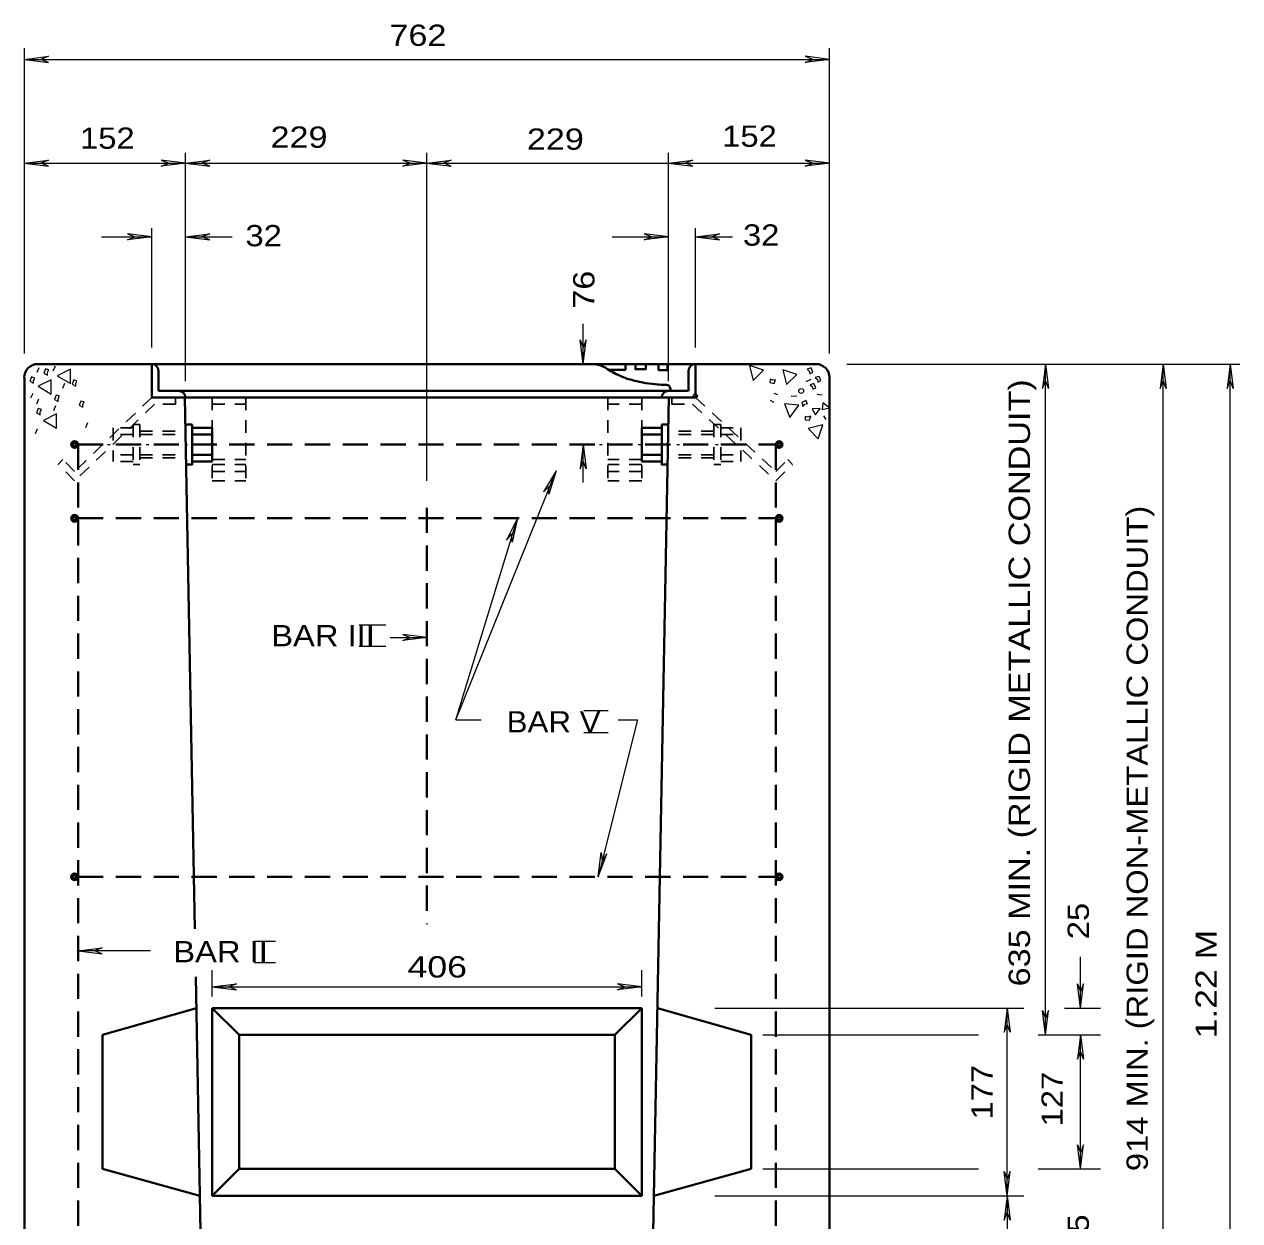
# Model space of a CAD drawing. Extents: x 312583 to 312854, y 144419 to 144597.
# Drawn here: x 312697 to 312740.39, y 144467.02 to 144509.75 of the extents above; entities that cross this region are included whole.
import ezdxf

# ---------------------------------------------------------------- set-up
doc = ezdxf.new("R2010")
doc.units = 0
doc.header["$LTSCALE"] = 0.3
doc.header["$PDMODE"] = 32
doc.header["$PDSIZE"] = 0.15
for name, pattern in [('DOTTED', [1.5, 0.3, -1.2]), ('MEDIUM_DASHED', [4.5, 3, -1.5]), ('SHORT_DASHED', [2.7, 1.5, -1.2])]:
    doc.linetypes.add(name, pattern=pattern)
doc.layers.add('1', color=7, linetype='Continuous', lineweight=25)
doc.layers.add('2', color=7, linetype='Continuous', lineweight=13)

msp = doc.modelspace()

# ---------------------------------------------------------------- linework, layer by layer
at = {"layer": '1', "lineweight": 13}
for p, q in [((312697.5224, 144497.485), (312697.4457, 144497.3164)), ((312698.0974, 144497.5387), (312698.0207, 144497.3624)), ((312697.3, 144496.565), (312697.2234, 144496.3964)), ((312698.4347, 144496.9177), (312698.358, 144496.749)), ((312697.507, 144496.358), (312697.4304, 144496.1894)), ((312698.1127, 144496.1204), (312698.036, 144495.9517)), ((312697.461, 144495.2924), (312697.3844, 144495.1237)), ((312699.255, 144495.5147), (312699.186, 144495.3384))]:
    msp.add_line(p, q, dxfattribs=at)
at = {"layer": '1', "lineweight": 40}
for p, q in [((312697.4764, 144497.6154), (312725.268, 144497.6154)), ((312701.5474, 144497.6154), (312701.5474, 144496.4194)), ((312720.9594, 144497.6154), (312720.9594, 144496.4194)), ((312697.001, 144497.14), (312697.001, 144451.6154)), ((312701.7927, 144497.3777), (312701.7927, 144496.657)), ((312720.714, 144497.3777), (312720.714, 144496.657)), ((312725.751, 144497.14), (312725.751, 144451.6154)), ((312701.7927, 144496.657), (312720.714, 144496.657)), ((312701.5474, 144496.4194), (312720.9594, 144496.4194)), ((312702.728, 144496.4194), (312703.0884, 144477.4444)), ((312720.0164, 144496.4194), (312719.2804, 144457.3654)), ((312702.9887, 144495.461), (312702.751, 144495.461)), ((312702.9887, 144495.3384), (312703.7094, 144495.3384)), ((312703.7094, 144495.3384), (312703.7094, 144494.1424)), ((312719.0427, 144495.3384), (312719.0427, 144494.1424)), ((312719.7557, 144495.3384), (312719.0427, 144495.3384)), ((312719.7557, 144495.461), (312720.001, 144495.461)), ((312702.9887, 144495.1007), (312703.7094, 144495.1007)), ((312719.7557, 144495.1007), (312719.0427, 144495.1007)), ((312702.9887, 144494.38), (312703.7094, 144494.38)), ((312702.9887, 144494.1424), (312703.7094, 144494.1424)), ((312719.7557, 144494.38), (312719.0427, 144494.38)), ((312719.7557, 144494.1424), (312719.0427, 144494.1424)), ((312703.119, 144475.727), (312703.464, 144457.3654)), ((312703.142, 144474.6154), (312699.7917, 144473.657)), ((312703.7094, 144474.6154), (312719.0427, 144474.6154)), ((312703.7094, 144474.6154), (312703.7094, 144467.907)), ((312704.6677, 144473.657), (312703.7094, 144474.6154)), ((312718.0844, 144473.657), (312719.0427, 144474.6154)), ((312719.0427, 144474.6154), (312719.0427, 144467.907)), ((312719.6024, 144474.6154), (312722.9527, 144473.657)), ((312699.7917, 144473.657), (312699.7917, 144468.8654)), ((312704.6677, 144473.657), (312718.0844, 144473.657)), ((312704.6677, 144473.657), (312704.6677, 144468.8654)), ((312718.0844, 144473.657), (312718.0844, 144468.8654)), ((312722.9527, 144473.657), (312722.9527, 144468.8654)), ((312699.7917, 144468.8654), (312703.2647, 144467.907)), ((312704.6677, 144468.8654), (312703.7094, 144467.907)), ((312704.6677, 144468.8654), (312718.0844, 144468.8654)), ((312719.0427, 144467.907), (312718.0844, 144468.8654)), ((312722.9527, 144468.8654), (312719.4797, 144467.907)), ((312703.7094, 144467.907), (312719.0427, 144467.907))]:
    msp.add_line(p, q, dxfattribs=at)
at = {"layer": '1', "linetype": 'SHORT_DASHED'}
for p, q in [((312701.5474, 144496.4194), (312698.795, 144493.782)), ((312701.647, 144496.1817), (312698.795, 144493.4447)), ((312702.3907, 144496.1817), (312701.647, 144496.1817)), ((312702.3907, 144496.4194), (312702.3907, 144496.1817)), ((312703.7094, 144496.4194), (312703.7094, 144493.4447)), ((312703.7094, 144496.1817), (312704.9054, 144496.1817)), ((312704.9054, 144496.4194), (312704.9054, 144493.4447)), ((312717.839, 144496.4194), (312717.839, 144493.4447)), ((312719.0427, 144496.1817), (312717.839, 144496.1817)), ((312719.0427, 144496.4194), (312719.0427, 144493.4447)), ((312720.116, 144496.4194), (312720.116, 144496.1817)), ((312720.116, 144496.1817), (312720.8597, 144496.1817)), ((312720.8597, 144496.1817), (312723.8344, 144493.4447)), ((312720.9594, 144496.4194), (312723.8344, 144493.782)), ((312700.1674, 144495.3384), (312700.1674, 144494.1424)), ((312700.888, 144495.3384), (312700.1674, 144495.3384)), ((312700.888, 144495.461), (312700.888, 144494.0274)), ((312700.888, 144495.461), (312701.1257, 144495.461)), ((312701.1257, 144495.461), (312701.1257, 144494.0274)), ((312721.6187, 144495.461), (312721.6187, 144494.0274)), ((312721.864, 144495.461), (312721.6187, 144495.461)), ((312721.864, 144495.461), (312721.864, 144494.0274)), ((312721.864, 144495.3384), (312722.577, 144495.3384)), ((312722.577, 144495.3384), (312722.577, 144494.1424)), ((312700.888, 144495.1007), (312700.1674, 144495.1007)), ((312701.1257, 144495.2234), (312702.751, 144495.2234)), ((312701.1257, 144495.1007), (312702.751, 144495.1007)), ((312721.6187, 144495.2234), (312720.001, 144495.2234)), ((312721.6187, 144495.1007), (312720.001, 144495.1007)), ((312721.864, 144495.1007), (312722.577, 144495.1007)), ((312698.3734, 144494.2037), (312698.2047, 144494.035)), ((312698.795, 144493.4447), (312698.2047, 144494.035)), ((312698.795, 144493.782), (312698.3734, 144494.2037)), ((312700.888, 144494.38), (312700.1674, 144494.38)), ((312700.888, 144494.1424), (312700.1674, 144494.1424)), ((312700.888, 144494.0274), (312701.1257, 144494.0274)), ((312701.1257, 144494.38), (312702.751, 144494.38)), ((312701.1257, 144494.265), (312702.751, 144494.265)), ((312703.7094, 144494.2037), (312704.9054, 144494.2037)), ((312703.7094, 144494.035), (312704.9054, 144494.035)), ((312719.0427, 144494.2037), (312717.839, 144494.2037)), ((312719.0427, 144494.035), (312717.839, 144494.035)), ((312721.6187, 144494.38), (312720.001, 144494.38)), ((312721.6187, 144494.265), (312720.001, 144494.265)), ((312721.864, 144494.0274), (312721.6187, 144494.0274)), ((312721.864, 144494.38), (312722.577, 144494.38)), ((312721.864, 144494.1424), (312722.577, 144494.1424)), ((312723.8344, 144493.782), (312724.256, 144494.2037)), ((312723.8344, 144493.4447), (312724.4247, 144494.035)), ((312724.256, 144494.2037), (312724.4247, 144494.035)), ((312703.7094, 144493.782), (312704.9054, 144493.782)), ((312719.0427, 144493.782), (312717.839, 144493.782)), ((312703.7094, 144493.4447), (312704.9054, 144493.4447)), ((312719.0427, 144493.4447), (312717.839, 144493.4447))]:
    msp.add_line(p, q, dxfattribs=at)
at = {"layer": '1', "linetype": 'MEDIUM_DASHED', "lineweight": 40}
for p, q in [((312698.9177, 144494.7404), (312698.9177, 144452.9187)), ((312698.9177, 144494.7404), (312723.8344, 144494.7404)), ((312723.8344, 144494.7404), (312723.8344, 144452.9187)), ((312711.376, 144492.4864), (312711.376, 144477.6054)), ((312698.9177, 144492.1107), (312723.8344, 144492.1107)), ((312698.9177, 144479.2997), (312723.8344, 144479.2997))]:
    msp.add_line(p, q, dxfattribs=at)
at = {"layer": '1', "linetype": 'DOTTED', "lineweight": 13}
for p, q in [((312699.968, 144494.7404), (312704.0007, 144494.7404)), ((312716.6124, 144494.7404), (312722.9067, 144494.7404))]:
    msp.add_line(p, q, dxfattribs=at)
at = {"layer": '1', "lineweight": 13}
for points in [[(312697.829, 144497.324), (312697.875, 144497.4084), (312697.76, 144497.4467), (312697.6987, 144497.2934), (312697.829, 144497.2167)], [(312698.6417, 144496.9177), (312698.6417, 144497.439), (312698.174, 144497.2014)], [(312697.323, 144497.0327), (312697.369, 144497.117), (312697.254, 144497.1554), (312697.1927, 144497.002), (312697.323, 144496.933)], [(312697.9594, 144496.542), (312697.9594, 144497.0557), (312697.4917, 144496.8257)], [(312698.8334, 144496.933), (312698.8794, 144497.0097), (312698.7644, 144497.048), (312698.703, 144496.8947), (312698.8334, 144496.8257)], [(312698.2124, 144496.3887), (312698.2584, 144496.4654), (312698.1357, 144496.5037), (312698.082, 144496.3504), (312698.2124, 144496.2814)], [(312699.0864, 144496.1817), (312699.1324, 144496.266), (312699.0174, 144496.2967), (312698.956, 144496.1434), (312699.0864, 144496.0744)], [(312697.5607, 144495.9134), (312697.6067, 144495.99), (312697.4917, 144496.0284), (312697.4304, 144495.875), (312697.5607, 144495.806)], [(312698.151, 144495.3307), (312698.151, 144495.8444), (312697.6834, 144495.6067)]]:
    msp.add_lwpolyline(points, close=True, dxfattribs=at)
at = {"layer": '1', "lineweight": 40}
for points in [[(312718.46, 144497.6154), (312718.46, 144497.416), (312717.8927, 144497.416)], [(312702.9887, 144495.461), (312702.9887, 144494.0274), (312702.751, 144494.0274)], [(312719.7557, 144495.461), (312719.7557, 144494.0274), (312720.001, 144494.0274)]]:
    msp.add_lwpolyline(points, dxfattribs=at)
for points in [[(312718.8204, 144497.6154), (312718.8204, 144497.4314), (312719.1884, 144497.4314), (312719.1884, 144497.6154)], [(312719.6484, 144497.6154), (312719.6484, 144497.4007), (312719.9627, 144497.4007), (312719.9627, 144497.6154)]]:
    msp.add_lwpolyline(points, close=True, dxfattribs=at)
for centre, radius in [((312698.795, 144494.7423), 0.1198), ((312698.795, 144494.7423), 0.0838), ((312723.9513, 144494.7423), 0.1198), ((312723.9513, 144494.7423), 0.0838), ((312698.795, 144494.7423), 0.0587), ((312723.9513, 144494.7423), 0.0587), ((312698.795, 144492.1069), 0.1198), ((312723.9513, 144492.1069), 0.1198), ((312698.795, 144492.1069), 0.0838), ((312698.795, 144492.1069), 0.0587), ((312723.9513, 144492.1069), 0.0838), ((312723.9513, 144492.1069), 0.0587), ((312698.795, 144479.3026), 0.1198), ((312698.795, 144479.3026), 0.0838), ((312698.795, 144479.3026), 0.0587), ((312723.9513, 144479.3026), 0.1198), ((312723.9513, 144479.3026), 0.0838), ((312723.9513, 144479.3026), 0.0587)]:
    msp.add_circle(centre, radius, dxfattribs=at)
for centre, radius, start, end in [((312697.4773, 144497.1381), 0.4792, 90, 180), ((312701.5502, 144497.3777), 0.2396, 0, 90), ((312720.9565, 144497.3777), 0.2396, 90, 180), ((312725.269, 144497.1381), 0.4792, 0, 90), ((312702.5086, 144496.4194), 0.2396, 0, 90), ((312719.9982, 144496.4194), 0.2396, 90, 180)]:
    msp.add_arc(centre, radius, start, end, dxfattribs=at)
msp.add_spline([(312717.379, 144497.6154), (312717.586, 144497.5617), (312717.7624, 144497.4774), (312718.0077, 144497.324), (312718.2684, 144497.2014), (312718.4217, 144497.1324), (312718.6364, 144497.0634), (312719.081, 144496.956), (312719.518, 144496.9024), (312719.8324, 144496.8717), (312720.0087, 144496.8487), (312720.0777, 144496.657)], degree=3, dxfattribs=at)
at = {"layer": '2'}
for p, q in [((312697.001, 144497.9987), (312697.001, 144508.9007)), ((312725.751, 144497.9987), (312725.751, 144508.9007)), ((312697.001, 144508.502), (312697.8674, 144508.6094)), ((312697.001, 144508.502), (312725.751, 144508.502)), ((312697.001, 144508.502), (312697.8674, 144508.3947)), ((312697.8674, 144508.6094), (312697.5914, 144508.502)), ((312697.8674, 144508.3947), (312697.5914, 144508.502)), ((312724.8847, 144508.6094), (312725.1607, 144508.502)), ((312725.751, 144508.502), (312724.8847, 144508.6094)), ((312724.8847, 144508.3947), (312725.1607, 144508.502)), ((312725.751, 144508.502), (312724.8847, 144508.3947)), ((312697.001, 144504.7914), (312697.8674, 144504.8987)), ((312697.8674, 144504.8987), (312697.5914, 144504.7914)), ((312701.8847, 144504.8987), (312702.1607, 144504.7914)), ((312702.751, 144504.7914), (312701.8847, 144504.8987)), ((312702.751, 144497.002), (312702.751, 144505.167)), ((312702.751, 144504.7914), (312703.6174, 144504.8987)), ((312703.6174, 144504.8987), (312703.3414, 144504.7914)), ((312710.5097, 144504.8987), (312710.7857, 144504.7914)), ((312711.376, 144504.7914), (312710.5097, 144504.8987)), ((312711.376, 144493.4447), (312711.376, 144505.167)), ((312711.376, 144504.7914), (312712.2424, 144504.8987)), ((312712.2424, 144504.8987), (312711.9664, 144504.7914)), ((312720.001, 144497.002), (312720.001, 144505.167)), ((312720.001, 144504.7914), (312720.8674, 144504.8987)), ((312720.8674, 144504.8987), (312720.5914, 144504.7914)), ((312724.8847, 144504.8987), (312725.1607, 144504.7914)), ((312725.751, 144504.7914), (312724.8847, 144504.8987)), ((312697.001, 144504.7914), (312702.751, 144504.7914)), ((312697.001, 144504.7914), (312697.8674, 144504.684)), ((312697.8674, 144504.684), (312697.5914, 144504.7914)), ((312701.8847, 144504.684), (312702.1607, 144504.7914)), ((312702.751, 144504.7914), (312701.8847, 144504.684)), ((312702.751, 144504.7914), (312711.376, 144504.7914)), ((312702.751, 144504.7914), (312703.6174, 144504.684)), ((312703.6174, 144504.684), (312703.3414, 144504.7914)), ((312710.5097, 144504.684), (312710.7857, 144504.7914)), ((312711.376, 144504.7914), (312710.5097, 144504.684)), ((312711.376, 144504.7914), (312720.001, 144504.7914)), ((312711.376, 144504.7914), (312712.2424, 144504.684)), ((312712.2424, 144504.684), (312711.9664, 144504.7914)), ((312720.001, 144504.7914), (312725.751, 144504.7914)), ((312720.001, 144504.7914), (312720.8674, 144504.684)), ((312720.8674, 144504.684), (312720.5914, 144504.7914)), ((312724.8847, 144504.684), (312725.1607, 144504.7914)), ((312725.751, 144504.7914), (312724.8847, 144504.684)), ((312700.681, 144502.269), (312700.957, 144502.1617)), ((312701.5474, 144502.1617), (312700.681, 144502.269)), ((312701.5474, 144498.2134), (312701.5474, 144502.476)), ((312702.751, 144502.1617), (312703.6174, 144502.269)), ((312703.6174, 144502.269), (312703.3414, 144502.1617)), ((312719.1347, 144502.269), (312719.4107, 144502.1617)), ((312720.001, 144502.1617), (312719.1347, 144502.269)), ((312720.9594, 144498.2134), (312720.9594, 144502.476)), ((312720.9594, 144502.1617), (312721.8257, 144502.269)), ((312721.8257, 144502.269), (312721.5497, 144502.1617)), ((312699.7534, 144502.1617), (312701.5474, 144502.1617)), ((312700.681, 144502.0544), (312700.957, 144502.1617)), ((312701.5474, 144502.1617), (312700.681, 144502.0544)), ((312702.751, 144502.1617), (312704.4224, 144502.1617)), ((312702.751, 144502.1617), (312703.6174, 144502.0544)), ((312703.6174, 144502.0544), (312703.3414, 144502.1617)), ((312717.9924, 144502.1617), (312720.001, 144502.1617)), ((312719.1347, 144502.0544), (312719.4107, 144502.1617)), ((312720.001, 144502.1617), (312719.1347, 144502.0544)), ((312720.9594, 144502.1617), (312722.2857, 144502.1617)), ((312720.9594, 144502.1617), (312721.8257, 144502.0544)), ((312721.8257, 144502.0544), (312721.5497, 144502.1617)), ((312716.9497, 144497.6154), (312716.9497, 144499.0567)), ((312716.8424, 144498.4817), (312716.9497, 144498.2057)), ((312716.9497, 144497.6154), (312716.8424, 144498.4817)), ((312717.057, 144498.4817), (312716.9497, 144498.2057)), ((312716.9497, 144497.6154), (312717.057, 144498.4817)), ((312726.3644, 144497.6154), (312740.3944, 144497.6154)), ((312733.456, 144497.6154), (312733.3487, 144496.749)), ((312733.456, 144473.657), (312733.456, 144497.6154)), ((312733.456, 144497.6154), (312733.5634, 144496.749)), ((312737.665, 144497.6154), (312737.5577, 144496.749)), ((312737.665, 144463.1154), (312737.665, 144497.6154)), ((312737.665, 144497.6154), (312737.7724, 144496.749)), ((312740.057, 144497.6154), (312739.9497, 144496.749)), ((312740.057, 144451.6154), (312740.057, 144497.6154)), ((312740.057, 144497.6154), (312740.1644, 144496.749)), ((312725.084, 144497.071), (312724.9077, 144496.979)), ((312733.3487, 144496.749), (312733.456, 144497.025)), ((312733.5634, 144496.749), (312733.456, 144497.025)), ((312737.5577, 144496.749), (312737.665, 144497.025)), ((312737.7724, 144496.749), (312737.665, 144497.025)), ((312739.9497, 144496.749), (312740.057, 144497.025)), ((312740.1644, 144496.749), (312740.057, 144497.025)), ((312723.7577, 144496.5727), (312723.8957, 144496.5344)), ((312723.635, 144496.3274), (312723.7577, 144496.2507)), ((312724.5857, 144496.4654), (312724.3787, 144496.4577)), ((312725.4827, 144496.5114), (312725.3064, 144496.5344)), ((312725.6284, 144495.6374), (312725.5517, 144495.7677)), ((312716.9497, 144494.7404), (312716.8424, 144493.874)), ((312716.9497, 144494.7404), (312717.057, 144493.874)), ((312716.9497, 144493.391), (312716.9497, 144494.7404)), ((312716.8424, 144493.874), (312716.9497, 144494.15)), ((312717.057, 144493.874), (312716.9497, 144494.15)), ((312712.411, 144484.9117), (312715.9914, 144493.7974)), ((312715.9914, 144493.7974), (312715.5314, 144493.0537)), ((312715.9914, 144493.7974), (312715.7307, 144492.9694)), ((312715.5314, 144493.0537), (312715.746, 144493.2607)), ((312715.7307, 144492.9694), (312715.746, 144493.2607)), ((312712.411, 144484.9117), (312714.6037, 144492.1107)), ((312714.6037, 144492.1107), (312714.2127, 144491.3287)), ((312714.6037, 144492.1107), (312714.4197, 144491.252)), ((312714.2127, 144491.3287), (312714.4044, 144491.551)), ((312714.4197, 144491.252), (312714.4044, 144491.551)), ((312708.9534, 144488.299), (312709.9117, 144488.299)), ((312710.5097, 144487.9554), (312710.7857, 144487.848)), ((312711.376, 144487.848), (312710.5097, 144487.9554)), ((312708.9534, 144487.541), (312709.9117, 144487.541)), ((312710.0574, 144487.848), (312711.376, 144487.848)), ((312710.5097, 144487.7407), (312710.7857, 144487.848)), ((312711.376, 144487.848), (312710.5097, 144487.7407)), ((312712.411, 144484.9117), (312713.3157, 144484.9117)), ((312716.9727, 144485.2443), (312717.8467, 144485.2443)), ((312718.897, 144484.9117), (312717.4864, 144479.2997)), ((312718.207, 144484.9117), (312718.897, 144484.9117)), ((312716.9727, 144484.4552), (312717.8467, 144484.4552)), ((312717.4864, 144479.2997), (312717.5937, 144480.166)), ((312717.4864, 144479.2997), (312717.8007, 144480.12)), ((312717.5937, 144480.166), (312717.632, 144479.8747)), ((312717.8007, 144480.12), (312717.632, 144479.8747)), ((312698.9177, 144476.6624), (312699.784, 144476.7697)), ((312701.5014, 144476.6624), (312698.9177, 144476.6624)), ((312698.9177, 144476.6624), (312699.784, 144476.555)), ((312699.784, 144476.7697), (312699.508, 144476.6624)), ((312699.784, 144476.555), (312699.508, 144476.6624)), ((312705.212, 144477.0072), (312705.971, 144477.0072)), ((312705.212, 144476.2448), (312705.971, 144476.2448)), ((312734.7057, 144474.6154), (312734.7057, 144476.4477)), ((312703.7094, 144475.0294), (312703.7094, 144475.9724)), ((312719.0427, 144475.0294), (312719.0427, 144475.9724)), ((312703.7094, 144475.3667), (312704.5757, 144475.474)), ((312703.7094, 144475.3667), (312719.0427, 144475.3667)), ((312703.7094, 144475.3667), (312704.5757, 144475.2594)), ((312704.5757, 144475.474), (312704.2997, 144475.3667)), ((312704.5757, 144475.2594), (312704.2997, 144475.3667)), ((312718.1764, 144475.474), (312718.4524, 144475.3667)), ((312719.0427, 144475.3667), (312718.1764, 144475.474)), ((312718.1764, 144475.2594), (312718.4524, 144475.3667)), ((312719.0427, 144475.3667), (312718.1764, 144475.2594)), ((312734.5984, 144475.4817), (312734.7057, 144475.2057)), ((312734.7057, 144474.6154), (312734.5984, 144475.4817)), ((312734.813, 144475.4817), (312734.7057, 144475.2057)), ((312734.7057, 144474.6154), (312734.813, 144475.4817)), ((312721.657, 144474.6154), (312732.6894, 144474.6154)), ((312732.0914, 144474.6154), (312731.984, 144473.749)), ((312732.0914, 144467.907), (312732.0914, 144474.6154)), ((312732.0914, 144474.6154), (312732.1987, 144473.749)), ((312733.3487, 144474.5234), (312733.456, 144474.2474)), ((312733.456, 144473.657), (312733.3487, 144474.5234)), ((312733.5634, 144474.5234), (312733.456, 144474.2474)), ((312733.456, 144473.657), (312733.5634, 144474.5234)), ((312734.1384, 144474.6154), (312735.4187, 144474.6154)), ((312731.984, 144473.749), (312732.0914, 144474.025)), ((312732.1987, 144473.749), (312732.0914, 144474.025)), ((312723.3667, 144473.657), (312731.064, 144473.657)), ((312733.203, 144473.657), (312735.4187, 144473.657)), ((312734.7057, 144473.657), (312734.5984, 144472.7907)), ((312734.7057, 144468.8654), (312734.7057, 144473.657)), ((312734.7057, 144473.657), (312734.813, 144472.7907)), ((312734.5984, 144472.7907), (312734.7057, 144473.0667)), ((312734.813, 144472.7907), (312734.7057, 144473.0667)), ((312734.5984, 144469.7317), (312734.7057, 144469.4557)), ((312734.7057, 144468.8654), (312734.5984, 144469.7317)), ((312734.813, 144469.7317), (312734.7057, 144469.4557)), ((312734.7057, 144468.8654), (312734.813, 144469.7317)), ((312723.3667, 144468.8654), (312731.064, 144468.8654)), ((312733.203, 144468.8654), (312735.4187, 144468.8654)), ((312731.984, 144468.7734), (312732.0914, 144468.4974)), ((312732.0914, 144467.907), (312731.984, 144468.7734)), ((312732.1987, 144468.7734), (312732.0914, 144468.4974)), ((312732.0914, 144467.907), (312732.1987, 144468.7734)), ((312721.657, 144467.907), (312732.6894, 144467.907)), ((312732.0914, 144467.907), (312731.984, 144467.0407)), ((312732.0914, 144467.907), (312732.0914, 144463.1154)), ((312732.0914, 144467.907), (312732.1987, 144467.0407)), ((312731.984, 144467.0407), (312732.0914, 144467.3167)), ((312732.1987, 144467.0407), (312732.0914, 144467.3167))]:
    msp.add_line(p, q, dxfattribs=at)
for points in [[(312723.0217, 144497.0327), (312723.3897, 144497.4007), (312722.8914, 144497.5617)], [(312725.0227, 144497.3624), (312725.0457, 144497.2704), (312725.153, 144497.3317), (312725.0917, 144497.4774), (312724.946, 144497.439)], [(312723.7194, 144497.0404), (312723.6274, 144497.0787), (312723.612, 144496.956), (312723.773, 144496.9177), (312723.819, 144497.0557)], [(312724.21, 144496.887), (312724.578, 144497.2474), (312724.0797, 144497.416)], [(312725.314, 144497.0634), (312725.337, 144496.9714), (312725.4444, 144497.0327), (312725.3754, 144497.1784), (312725.2374, 144497.14)], [(312725.13, 144496.8104), (312725.153, 144496.7184), (312725.2604, 144496.772), (312725.1914, 144496.9254), (312725.0534, 144496.8794)], [(312724.6547, 144496.151), (312724.141, 144496.197), (312724.3327, 144495.714)], [(312724.8694, 144496.1817), (312724.9614, 144496.2047), (312724.9, 144496.312), (312724.7544, 144496.243), (312724.7927, 144496.105)], [(312725.5134, 144496.2354), (312725.4827, 144495.99), (312725.751, 144496.059)], [(312724.969, 144495.7217), (312724.877, 144495.7447), (312724.877, 144495.622), (312725.038, 144495.6144), (312725.0764, 144495.7524)], [(312725.13, 144496.013), (312725.2527, 144495.806), (312725.4137, 144496.0284)], [(312724.9844, 144495.3154), (312725.3447, 144494.9474), (312725.5134, 144495.4457)]]:
    msp.add_lwpolyline(points, close=True, dxfattribs=at)
msp.add_circle((312724.7374, 144496.6576), 0.0865, dxfattribs=at)
msp.add_point((312720.9594, 144496.4807), dxfattribs=at)

# ---------------------------------------------------------------- texts
for s, width, p in [('762 ', 1.2, (312710.0348, 144508.9822)), ('229 ', 1.2, (312705.7899, 144505.3425)), ('152 ', 1.15, (312721.9167, 144505.378)), ('152 ', 1.15, (312698.9872, 144505.307)), ('229 ', 1.2, (312714.9417, 144505.2716)), ('32 ', 1.15, (312704.8948, 144501.8253)), ('32 ', 1.15, (312722.6586, 144501.8464)), ('BAR III', 1.15, (312705.8132, 144487.5365)), ('BAR V', 1.1, (312714.2195, 144484.4579)), ('BAR II', 1.15, (312702.3169, 144476.2488)), ('406 ', 1.25, (312710.6824, 144475.705))]:
    msp.add_text(s, height=0.76, dxfattribs=dict(at, width=width)).set_placement(p)
for s, width, p in [('76 ', 1.2, (312717.3554, 144499.5954)), ('635 MIN. (RIGID METALLIC CONDUIT)', 1.2, (312732.9055, 144475.3888)), ('914 MIN. (RIGID NON-METALLIC CONDUIT)', 1.15, (312737.1145, 144468.7889)), ('25 ', 1.15, (312735.0088, 144477.0725)), ('1.22 M ', 1.25, (312739.5774, 144473.5266)), ('177 ', 1.15, (312731.5764, 144470.6334)), ('127 ', 1.15, (312734.0784, 144470.3852)), ('25 ', 1.15, (312735.0088, 144465.9414))]:
    msp.add_text(s, height=0.76, rotation=90, dxfattribs=dict(at, width=width)).set_placement(p)

doc.saveas('drawing.dxf')
